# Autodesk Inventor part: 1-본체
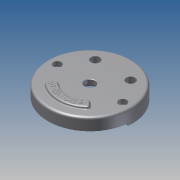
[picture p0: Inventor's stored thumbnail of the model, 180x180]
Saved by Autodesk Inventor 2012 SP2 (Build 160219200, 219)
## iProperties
Created: 2015-04
Part Number: 1-본체
Material: Default
Document SubType Name: Modeling
Designer: Administrator
Density: 1 g/cm^3
Author: Administrator
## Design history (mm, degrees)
sketch "스케치1"
  geometry: C1 r 95 at (0, 0); 1 further point
  constraints: 1 centre point, 1 coincident
  dimensions: "d0" = 190 diameter of C1
extrude "돌출1" new body sketch "스케치1" distance "d1" = 32; taper "d2" = 0 deg
sketch "스케치4"
  geometry: C1 r 95 at (0, 0) reference; C2 r 90 at (0, 0)
  constraints: 1 centre point, 1 coincident
  dimensions: "d14" = 180 diameter of C2
extrude "돌출3" cut sketch "스케치4" distance "d15" = 18; taper "d16" = 0 deg
sketch "스케치5"
  geometry: L1 (-95, 0)-(95, 0); L2 (0, 0)-(-89.658, -7.844); L3 (0, 0)-(89.658, -7.844); L4 (89.658, -7.844)-(94.638, -8.28); L5 (-89.658, -7.844)-(-94.638, -8.28); A1 r 90 centre (0, 0) between (89.658, -7.844) and (-89.658, -7.844) reference; A2 r 95 centre (0, 0) between (-95, 0) and (95, 0) reference
  constraints: 10 end point, 6 point on circle, 2 collinear, 1 coincident, 1 horizontal, 1 midpoint
  dimensions: "d17" = 5 deg angle of L3 L1; "d18" = 5 deg angle of L2 L1
extrude "돌출4" cut sketch "스케치5" distance "d19" = 5; taper "d20" = 0 deg
sketch "스케치6"
  geometry: L1 (-89.196, 12)-(-76.916, 12); L2 (40.249, 12)-(47.117, 12); L3 (-76.916, 12)-(-47.117, 12); L4 (-47.117, 12)-(-40.249, 12); L5 (47.117, 12)-(76.916, 12); L6 (76.916, 12)-(89.196, 12); A1 r 90 centre (0, 0) between (-89.196, 12) and (89.196, 12) reference; A2 r 42 centre (0, 0) between (-38.056, 17.769) and (38.056, 17.769); A3 r 10 centre (-76.916, 22) between (-86.53, 24.75) and (-76.916, 12); A4 r 10 centre (-47.117, 22) between (-47.117, 12) and (-38.056, 17.769); A5 r 10 centre (47.117, 22) between (38.056, 17.769) and (47.117, 12); A6 r 10 centre (76.916, 22) between (76.916, 12) and (86.53, 24.75); A7 r 90 centre (0, 0) between (89.658, -7.844) and (-89.658, -7.844) reference; A8 r 10 centre (-76.916, 22) between (-76.916, 12) and (-86.53, 24.75); A9 r 10 centre (-47.117, 22) between (-38.056, 17.769) and (-47.117, 12); A10 r 10 centre (47.117, 22) between (47.117, 12) and (38.056, 17.769); A11 r 10 centre (76.916, 22) between (86.53, 24.75) and (76.916, 12); A12 r 42 centre (0, 0) between (38.056, 17.769) and (-38.056, 17.769); 4 further points
  constraints: 26 point on circle, 16 tangent, 12 end point, 10 centre point, 6 horizontal, 4 midpoint, 2 point on line, 1 coincident, 1 horizontal alignment
  dimensions: "d21" = 84 diameter of A2; "d23" = 20 diameter of A3; "d24" = 20 diameter of A4; "d25" = 20 diameter of A5; "d26" = 20 diameter of A6; "d29" = 12 vertical distance of point (-62.016, 12) A1.centre
extrude "돌출5" cut sketch "스케치6" distance "d30" = 7; taper "d31" = 0 deg
sketch "스케치7"
  geometry: C1 r 35 at (0, 0); A1 r 42 centre (0, 0) between (38.056, 17.769) and (-38.056, 17.769) reference
  constraints: 1 centre point, 1 coincident
  dimensions: "d32" = 70 diameter of C1
extrude "돌출6" join sketch "스케치7" distance "d33" = 10; taper "d34" = -10 deg
sketch "스케치8"
  geometry: L1 (47.117, 12)-(76.916, 12) reference; L2 (0, 95)-(0, 0); C1 r 15 at (-40, 52); C2 r 15 at (40, 52); A1 r 42 centre (0, 0) between (38.056, 17.769) and (-38.056, 17.769) reference
  constraints: 2 centre point, 2 end point, 1 horizontal alignment, 1 perpendicular, 1 symmetric about line, 1 vertical alignment, 1 other
  dimensions: "d35" = 30 diameter of C1; "d36" = 30 diameter of C2; "d37" = 52 vertical distance of A1.centre C2.centre; "d38" = 80 distance of C2.centre C1.centre
extrude "돌출7" join sketch "스케치8" distance "d39" = 25; taper "d40" = 0 deg
sketch "스케치9"
  geometry: L1 (-47.117, 12)-(-76.916, 12) reference; L2 (0, 0)-(0, -95); C1 r 35 at (0, 0) reference; C2 r 9 at (-74, 0); C3 r 9 at (74, 0)
  constraints: 2 centre point, 2 end point, 2 horizontal alignment, 1 perpendicular, 1 symmetric about line, 1 vertical alignment, 1 other
  dimensions: "d41" = 18 diameter of C2; "d42" = 18 diameter of C3; "d43" = 148 distance of C3.centre C2.centre
extrude "돌출8" join sketch "스케치9" distance "d44" = 18; taper "d45" = 0 deg
sketch "스케치10"
  geometry: L1 (-47.117, 12)-(-76.916, 12) reference; L2 (0, 0)-(90, 0); L3 (0, 0)-(0, -95); C1 r 35 at (0, 0) reference; A1 r 90 centre (0, 0) between (-86.53, 24.75) and (86.53, 24.75) reference; A2 r 59 centre (0, -19) between (0, -78) and (58.704, -13.1); A3 r 41 centre (0, -19) between (0, -60) and (40.794, -14.9); A4 r 9 centre (-49.749, -14) between (-40.794, -14.9) and (-58.704, -13.1); A5 r 9 centre (49.749, -14) between (58.704, -13.1) and (40.794, -14.9); A6 r 59 centre (0, -19) between (-58.704, -13.1) and (0, -78); A7 r 59 centre (0, -19) between (58.704, -13.1) and (-58.704, -13.1); A8 r 41 centre (0, -19) between (-40.794, -14.9) and (0, -60); A9 r 41 centre (0, -19) between (40.794, -14.9) and (-40.794, -14.9); A10 r 9 centre (-49.749, -14) between (-58.704, -13.1) and (-40.794, -14.9); A11 r 9 centre (49.749, -14) between (40.794, -14.9) and (58.704, -13.1); 1 further point
  constraints: 21 point on circle, 10 centre point, 4 end point, 3 point on line, 2 tangent, 1 coincident, 1 horizontal alignment, 1 parallel, 1 perpendicular, 1 vertical alignment, 1 other
  dimensions: "d46" = 118 diameter of A2; "d47" = 82 diameter of A3; "d48" = 19 distance of A2.centre C1.centre; "d49" = 18 diameter of A4; "d50" = 18 diameter of A5; "d51" = 5 vertical distance of A5.centre A2.centre
extrude "돌출9" cut sketch "스케치10" distance "d52" = 7; taper "d53" = 0 deg
hole "구멍1" diameter "d56" = 20; stored, may be unused: countersink angle "d60" = 90 deg, drill point angle "d62" = 118 deg; dims "d54" = 10, "d55" = 10, "d57" = 6, "d58" = 4, "d59" = 2, "d61" = 8
hole "구멍2" diameter "d65" = 20; stored, may be unused: countersink angle "d69" = 90 deg, drill point angle "d71" = 118 deg; dims "d63" = 10, "d64" = 10, "d66" = 6, "d67" = 4, "d68" = 2, "d70" = 8
sketch "스케치11"
  geometry: C1 r 9 at (-74, 0) reference; C2 r 9 at (74, 0) reference; 2 further points
  constraints: 2 coincident
hole "구멍3" sketch "스케치11" at (-74, 0), (74, 0) diameter "d72" = 11; stored, may be unused: countersink angle "d76" = 90 deg, drill point angle "d78" = 118 deg; dims "d73" = 6, "d74" = 18, "d75" = 11, "d77" = 8
hole "구멍4" diameter "d81" = 50; stored, may be unused: countersink angle "d85" = 90 deg, drill point angle "d87" = 0 deg; dims "d79" = 10, "d80" = 10, "d82" = 6, "d83" = 4, "d84" = 2, "d86" = 15
hole "구멍5" diameter "d90" = 23; stored, may be unused: countersink angle "d94" = 90 deg, drill point angle "d96" = 0 deg; dims "d88" = 10, "d89" = 10, "d91" = 6, "d92" = 4, "d93" = 2, "d95" = 15
sketch "스케치12"
  geometry: L1 (0, 0)-(-36.062, -36.062); L2 (0, 0)-(36.062, -36.062); L3 (-39.44, -39.44)-(-47.244, -47.244); L4 (39.44, -39.44)-(47.244, -47.244); C1 r 11.5 at (0, 0) reference; A1 r 51 centre (0, 0) between (-32.699, -39.138) and (32.699, -39.138); A2 r 72 centre (0, 0) between (-46.97, -54.569) and (46.97, -54.569); A3 r 5 centre (-43.709, -50.78) between (-47.244, -47.244) and (-46.97, -54.569); A4 r 5 centre (-35.904, -42.975) between (-32.699, -39.138) and (-39.44, -39.44); A5 r 5 centre (35.904, -42.975) between (39.44, -39.44) and (32.699, -39.138); A6 r 5 centre (43.709, -50.78) between (46.97, -54.569) and (47.244, -47.244); 2 further points
  constraints: 16 point on circle, 8 end point, 8 tangent, 6 centre point, 4 point on line, 3 equal radius, 2 coincident, 2 collinear, 1 horizontal alignment
  dimensions: "d97" = 102 diameter of A1; "d99" = 90 deg angle of L2 L1; "d100" = 72 radius of A2; "d101" = 5 radius of A3
extrude "돌출10" join sketch "스케치12" distance "d102" = 5; taper "d103" = 0 deg
sketch "스케치13"
  geometry: C1 r 68 at (0, 0); A1 r 72 centre (0, 0) between (-46.97, -54.569) and (46.97, -54.569) reference
  constraints: 1 centre point, 1 coincident, 1 other
  dimensions: "d104" = 136 diameter of C1
feature "엠보싱1" sketch "스케치13" dims "d2" = 0, "d105" = 0.5, "d106" = 0
sketch "스케치14"
  geometry: L1 (-6, 13.748)-(-6, -13.748); L2 (6, 13.748)-(6, -13.748); L3 (66.252, 6)-(93.748, 6); L4 (66.252, -6)-(93.748, -6); L5 (0, 0)-(0, -15); L6 (80, 0)-(95, 0); C1 r 10 at (80, 0) reference; A1 r 15 centre (0, 0) between (-6, 13.748) and (-6, -13.748) reference; A2 r 15 centre (80, 0) between (66.252, 6) and (93.748, 6) reference; 1 further point
  constraints: 12 end point, 10 point on circle, 4 perpendicular, 1 horizontal, 1 vertical, 2 other
  dimensions: "d107" = 12 distance between parallel lines of L2 L1; "d108" = 12 distance between parallel lines of L4 L3
extrude "돌출11" cut sketch "스케치14" distance "d109" = 3; taper "d110" = 0 deg
fillet "모깎기1" dims "d111" = 3
fillet "모깎기2" dims "d112" = 2
fillet "모깎기3" dims "d113" = 5
fillet "모깎기4" dims "d114" = 0.3
fillet "모깎기5" dims "d115" = 3
chamfer "모따기1" distance "d116" = 1; stored, may be unused: second distance "d117" = 2, angle "d118" = 45 deg
fillet "모깎기6" dims "d119" = 3
fillet "모깎기7" dims "d120" = 1
chamfer "모따기2" distance "d121" = 1; stored, may be unused: second distance "d122" = 2, angle "d123" = 45 deg
node "솔리드1"
node "투영된 루프3"
other parameters: "d8" = 12, "d98" = 144
